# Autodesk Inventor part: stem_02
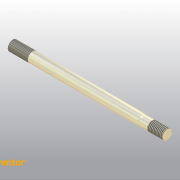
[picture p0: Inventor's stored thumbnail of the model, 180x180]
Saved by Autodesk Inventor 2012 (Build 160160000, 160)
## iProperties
Shininess: 64.0
Length Units: 11269
Angle Units: 11279
Time Units: 11290
Mass Units: 11283
Length Display Precision: 3
Angle Display Precision: 2
Company: Autodesk
Created: 2002-03
Part Number: stem_02
Document SubType Name: Modeling
Designer: Lieven Grauls
Stock Number: stem_02
Project: Valve Techcamp 2008
Density: 1 g/cm^3
Material: Default
Density: 0.0
Volumn: 0.0
Area: 0.0
PropertySet Name: Model Information
Control State: 0
Master: False
Checked Out: False
Author: Lieven Grauls
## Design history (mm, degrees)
sketch "Sketch1"
  geometry: L1 (0, 0)-(0, 6.335); L2 (0, 6.335)-(162.694, 6.335); L3 (174, 6)-(193, 6); L4 (193, 6)-(193, 0); L5 (193, 0)-(0, 0); L6 (174, 6)-(174, 5.985); L7 (174, 5.985)-(164, 5.985); L8 (164, 5.985)-(162.694, 6.335); 1 further point
  constraints: 16 end point, 2 parallel, 2 perpendicular, 1 coincident, 1 vertical
  dimensions: "d9" = 19 distance of L3.start L3.end; "d11" = 29 distance from line of L4 L7.end; "d12" = 15 deg angle of L2 L8; "d18" = 11.97 diameter of L7 L5; "d19" = 12 diameter of L3 L5; "d20" = 12.67 diameter of L2 L5; "d21" = 193 distance between parallel lines of L4 L1
revolve "Revolution1" sketch "Sketch1" stored, may be unused: angle "d13" = 90 deg
thread "Thread1" dims "d14" = 25, "d15" = 0
thread "Thread2" dims "d16" = 10, "d17" = 0
node "Volumenkörper1"
node "Volumenkörpern"
node "Oberflächenkörpern"
